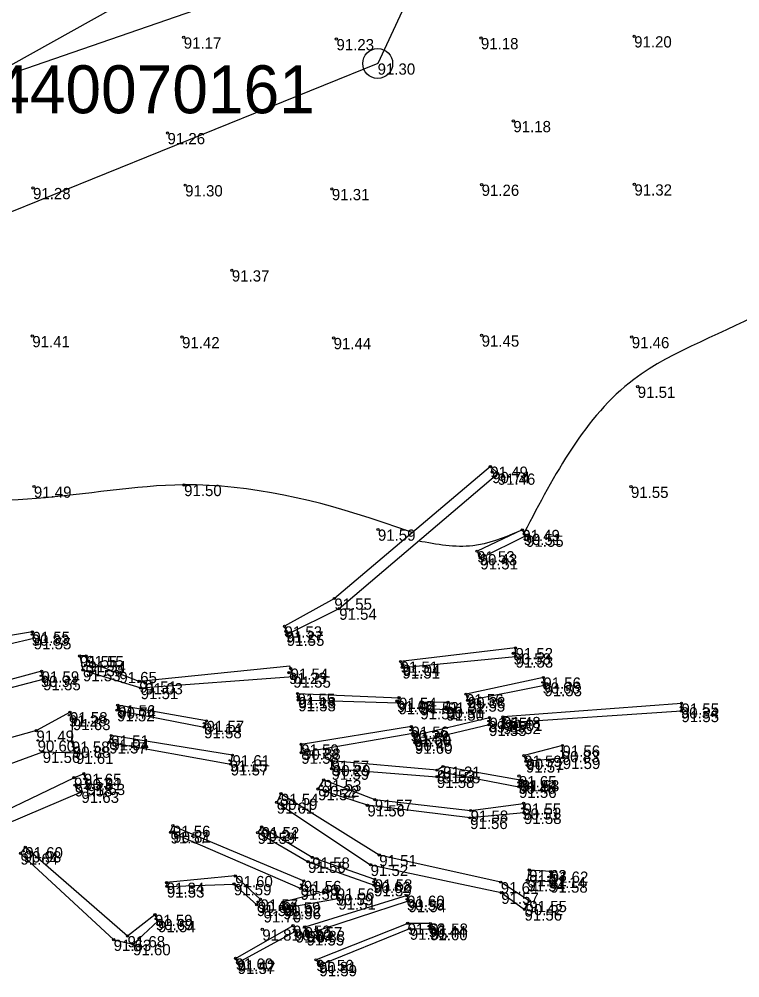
# Model space of a CAD drawing. Extents: x 316000 to 728450, y 314368 to 726000.
# Drawn here: x 725985.1 to 726225.7, y 315550.4 to 315870.5 of the extents above; entities that cross this region are included whole.
import ezdxf

# ---------------------------------------------------------------- set-up
doc = ezdxf.new("R2010")
doc.units = 0
for name, color, linetype in [('10', 7, 'Continuous'), ('24', 7, 'Continuous'), ('59', 7, 'Continuous'), ('HIDG_ELEM_####_####_#', 7, 'Continuous'), ('HIDG_GRAV_####_####_#', 7, 'Continuous'), ('RAMI_UZMR_####_####_#', 7, 'Continuous'), ('RELJ_AATZ_####_TKST_#', 7, 'Continuous'), ('RELJ_ELEM_####_####_#', 7, 'Continuous'), ('RELJ_HORZ_PAMT_####_#', 7, 'Continuous'), ('RELJ_NOGA_####_####_#', 7, 'Continuous')]:
    doc.layers.add(name, color=color, linetype=linetype)

msp = doc.modelspace()

# ---------------------------------------------------------------- linework, layer by layer
at = {"layer": '10'}
msp.add_circle((726104.77, 315855.74), 5, dxfattribs=at)
at = {"layer": '24'}
for p, q in [((726207.18, 316075.15), (726104.77, 315855.74)), ((726064.11, 315880.58), (725858.2, 315809.4)), ((726104.77, 315855.74), (725891.35, 315769.28))]:
    msp.add_line(p, q, dxfattribs=at)
at = {"layer": 'HIDG_ELEM_####_####_#'}
for centre in [(726143, 315719.32), (726153.49, 315698.65), (726138.81, 315691.88), (726074.12, 315666.08), (725989.22, 315665.03), (726150.07, 315658.75), (726007.24, 315654.78), (726113.08, 315654.96), (725992.27, 315651.23), (726075.17, 315652.25), (726027.17, 315648.78), (726159.77, 315649.04), (726078.33, 315644.09), (726111.18, 315642.84), (726134.88, 315644.17), (726018.16, 315640.71), (726127.64, 315640.86), (726206.01, 315640.73), (726001.65, 315638.05), (726147.28, 315636.57), (726046.73, 315635.38), (726115.69, 315633.07), (726141.74, 315636.09), (726015.83, 315630.07), (726117.25, 315629.89), (725991.21, 315629.64), (726002.99, 315627.6), (726079.86, 315626.93), (726154.44, 315623.57), (726166.25, 315626.08), (726055.39, 315622.97), (726089.81, 315621.42), (726006.78, 315616.78), (726086.09, 315614.52), (726151.71, 315615.59), (726072.09, 315610.2), (726153.04, 315606.94), (726036.49, 315599.24), (726065.62, 315599.79), (725986.55, 315592.63), (726103.26, 315582.42), (726155.35, 315584.71), (726161.79, 315584.06), (726079.11, 315581.52), (726064.74, 315575.79), (726090.72, 315578.33), (726114.45, 315576.61), (726073.4, 315574.64), (726154.14, 315575.01), (726030.67, 315570.02), (726076.82, 315566.55), (726081.3, 315566.04), (726121.77, 315567.65), (726057.93, 315556.25), (726085.14, 315555.68)]:
    msp.add_circle(centre, 0.225, dxfattribs=at)
at = {"layer": 'HIDG_GRAV_####_####_#'}
for points in [[(726073.66, 315667.76), (726074.41, 315664.99), (726091.92, 315673.69), (726144.85, 315718.79), (726142.39, 315721.11), (726090.3, 315677.06), (726073.66, 315667.76)], [(726137.95, 315692.86), (726139.05, 315690.52), (726154.31, 315698.07), (726153.07, 315699.99), (726137.95, 315692.86)], [(725971.42, 315662.89), (725972.67, 315659.82), (725989.93, 315663.82), (725989.49, 315665.92), (725971.42, 315662.89)], [(726112.4, 315656.01), (726113.03, 315654.06), (726150.83, 315657.71), (726150.78, 315660.52), (726112.4, 315656.01)], [(726008.23, 315655.95), (726007.42, 315657.87), (726005.29, 315657.85), (726006.36, 315653.15), (726025.63, 315647.19), (726076.58, 315651.01), (726075.42, 315654.44), (726025.17, 315649.38), (726008.23, 315655.95)], [(725947, 315640.41), (725947.4, 315638.23), (725993.06, 315650.14), (725992.55, 315652.74), (725947, 315640.41)], [(726134.27, 315645.11), (726134.79, 315643), (726160.44, 315648.16), (726160.1, 315650.67), (726134.27, 315645.11)], [(726111.91, 315643.92), (726111.73, 315642.13), (726078.25, 315643.12), (726078.05, 315645.31), (726111.91, 315643.92)], [(726017.97, 315641.42), (726017.73, 315639.76), (726046.83, 315634.1), (726047.62, 315636.2), (726017.97, 315641.42)], [(726119.29, 315642.48), (726119.01, 315640.43), (726127.73, 315640), (726128.24, 315642.37), (726119.29, 315642.48)], [(726146.64, 315637.5), (726146.7, 315635.52), (726206.19, 315639.5), (726206.22, 315642), (726146.64, 315637.5)], [(725961.77, 315624.89), (725965.2, 315615.66), (725992.91, 315625.87), (726004, 315625.55), (726002.67, 315629.29), (726003.02, 315636.83), (726002.03, 315639.09), (725990.81, 315632.94), (725961.77, 315624.89)], [(726142.11, 315637.26), (726141.95, 315634.87), (726117.19, 315628.94), (726116.81, 315631.3), (726142.11, 315637.26)], [(726079.23, 315628.32), (726079.27, 315625.6), (726116.55, 315632.09), (726116.04, 315634.27), (726079.23, 315628.32)], [(726015.78, 315631.3), (726015.12, 315629.03), (726055.71, 315621.71), (726056.28, 315624.72), (726015.78, 315631.3)], [(726153.67, 315624.58), (726154.26, 315622.67), (726166.57, 315623.84), (726166.49, 315627.96), (726153.67, 315624.58)], [(726089.35, 315622.87), (726089.35, 315620.25), (726124.54, 315617.51), (726126.5, 315619.06), (726151.96, 315614.2), (726152.32, 315616.35), (726126.61, 315620.93), (726124.62, 315619.71), (726089.35, 315622.87)], [(725965.8, 315599.1), (725967.37, 315596.09), (726005.84, 315612.53), (726003.63, 315614.7), (726007.88, 315615.15), (726006.65, 315618.54), (726003.38, 315617.21), (725965.8, 315599.1)], [(726153.48, 315608.61), (726153.62, 315605.48), (726135.63, 315603.8), (726101.33, 315608.01), (726084.88, 315613.42), (726086.77, 315616.44), (726103.83, 315609.87), (726135.8, 315606.24), (726153.48, 315608.61)], [(726072.46, 315611.83), (726071.06, 315608.94), (726102.41, 315588.11), (726146.04, 315578.8)], [(726145.87, 315582.31), (726105.29, 315591.35), (726072.46, 315611.83)], [(726035.58, 315598.99), (726036.38, 315601.14), (726080.09, 315582.74), (726079.03, 315580.18), (726035.58, 315598.99)], [(726064.7, 315598.85), (726081.53, 315589.14), (726103.55, 315581.33), (726103.81, 315583.25), (726082.93, 315590.56), (726066.03, 315600.7), (726064.7, 315598.85)], [(725987.1, 315594.01), (725985.49, 315591.9), (726016.61, 315563.09), (726023.09, 315561.62), (726031.43, 315569.34), (726030.39, 315571.42), (726021.24, 315564.3), (725987.1, 315594.01)], [(726155.37, 315586.36), (726154.76, 315582.96), (726162.37, 315582.55), (726162.55, 315585.85), (726155.37, 315586.36)], [(726034.3, 315582.14), (726034.39, 315580.91), (726056.76, 315581.68), (726064.39, 315574.73), (726065.64, 315576.57), (726057.2, 315584.38), (726034.3, 315582.14)], [(726146.04, 315578.8), (726153.8, 315573.21), (726155.39, 315576.05), (726145.87, 315582.31)], [(726073.1, 315575.61), (726073.24, 315573.67), (726091.62, 315576.87), (726091.12, 315580.22), (726073.1, 315575.61)], [(726080.4, 315567.3), (726081.03, 315564.91), (726115.03, 315576.03), (726114.6, 315577.81), (726080.4, 315567.3)], [(726076.5, 315567.8), (726077.4, 315565.89), (726058.02, 315555.39), (726057.33, 315556.83), (726076.5, 315567.8)], [(726084.19, 315556.36), (726085.31, 315554.63), (726115.49, 315566.82), (726122.24, 315566.65), (726122.35, 315568.49), (726114.79, 315568.52), (726084.19, 315556.36)]]:
    msp.add_lwpolyline(points, dxfattribs=at)
at = {"layer": 'RAMI_UZMR_####_####_#'}
msp.add_lwpolyline([(727254.69, 315085.95), (727002.7, 315002.84), (726508.21, 314868.03), (726416.7, 314837.05), (725982.38, 314530.96), (725916.44, 314513.26), (725799.16, 314549.2), (725735.9, 314623.63), (725701.82, 314711.1), (725697.25, 315112.64), (725659.91, 315163.35), (725614.81, 315211.65), (725561.8, 315231.45), (725500.09, 315274.21), (725474.77, 315308.26), (725484.26, 315374.77), (725505.03, 315405.04), (725554.87, 315404.25), (725559.14, 315567.14), (725558.67, 315591.68), (725662, 315676.73), (726089.69, 315915.19)], dxfattribs=at)
at = {"layer": 'RELJ_ELEM_####_####_#'}
for centre in [(726040.02, 315864.45), (726091, 315863.9), (726139.24, 315864.25), (726190.42, 315864.84), (726150.07, 315836.55), (726034.58, 315832.53), (725989.68, 315814.18), (726040.48, 315815.1), (726089.47, 315813.83), (726139.48, 315815.28), (726190.5, 315815.38), (726056.07, 315786.67), (725989.44, 315764.72), (726039.44, 315764.37), (726139.49, 315764.92), (726189.62, 315764.39), (726090.06, 315764.08), (726191.61, 315747.81), (726142.39, 315721.11), (726143, 315719.32), (726144.85, 315718.79), (725989.97, 315714.46), (726040.13, 315715), (726189.34, 315714.39), (726104.85, 315700.1), (726153.07, 315699.99), (726154.31, 315698.07), (726137.95, 315692.86), (726139.05, 315690.52), (726090.3, 315677.06), (726091.92, 315673.69), (725989.49, 315665.92), (726073.66, 315667.76), (726074.13, 315666.07), (726074.41, 315664.99), (726150.07, 315658.75), (726150.78, 315660.52), (726005.29, 315657.85), (726007.43, 315657.86), (726008.15, 315656.15), (726112.4, 315656.01), (726150.83, 315657.71), (725992.55, 315652.74), (726006.36, 315653.15), (726007.24, 315654.78), (726018.51, 315652.53), (726075.17, 315652.25), (726075.69, 315653.66), (726113.03, 315654.06), (726113.12, 315654.92), (725993.06, 315650.14), (726025.17, 315649.38), (726076.58, 315651.01), (726160.1, 315650.67), (726025.63, 315647.19), (726027.17, 315648.78), (726160.44, 315648.16), (726078, 315645.31), (726078.25, 315643.12), (726078.29, 315644.13), (726111.18, 315642.84), (726111.91, 315643.92), (726134.27, 315645.11), (726134.79, 315643), (726017.73, 315639.76), (726017.97, 315641.42), (726111.73, 315642.13), (726119.01, 315640.43), (726119.29, 315642.48), (726127.64, 315640.86), (726127.73, 315640), (726128.24, 315642.37), (726206.19, 315639.5), (726206.22, 315642), (726002.03, 315639.09), (726003.02, 315636.83), (726047.62, 315636.2), (726142.11, 315637.26), (726146.64, 315637.5), (725990.81, 315632.94), (726046.83, 315634.1), (726116.04, 315634.27), (726141.95, 315634.87), (726146.7, 315635.52), (726015.78, 315631.3), (726116.55, 315632.09), (726116.81, 315631.3), (726002.67, 315629.29), (726015.12, 315629.03), (726079.23, 315628.32), (726117.19, 315628.94), (726166.49, 315627.96), (725992.91, 315625.87), (726004, 315625.55), (726056.28, 315624.72), (726079.27, 315625.6), (726153.67, 315624.58), (726166.57, 315623.84), (726055.71, 315621.71), (726089.35, 315622.87), (726089.35, 315620.25), (726126.61, 315620.93), (726154.26, 315622.67), (726003.38, 315617.21), (726006.65, 315618.54), (726124.54, 315617.51), (726124.62, 315619.71), (726126.5, 315619.06), (726151.93, 315617.76), (726003.63, 315614.7), (726007.88, 315615.15), (726086.77, 315616.44), (726151.96, 315614.2), (726152.32, 315616.35), (726152.87, 315616.37), (726005.84, 315612.53), (726072.46, 315611.83), (726084.88, 315613.42), (726071.06, 315608.94), (726101.33, 315608.01), (726103.83, 315609.87), (726153.48, 315608.61), (726135.8, 315606.24), (726153.62, 315605.48), (726036.38, 315601.14), (726135.63, 315603.8), (726035.58, 315598.99), (726064.7, 315598.85), (726066.03, 315600.7), (725985.49, 315591.9), (725987.1, 315594.01), (726105.29, 315591.35), (726081.53, 315589.14), (726082.93, 315590.56), (726102.41, 315588.11), (726155.37, 315586.36), (726162.55, 315585.85), (726034.3, 315582.14), (726056.76, 315581.68), (726057.2, 315584.38), (726080.09, 315582.74), (726103.81, 315583.25), (726145.87, 315582.31), (726154.76, 315582.96), (726162.37, 315582.55), (726034.39, 315580.91), (726079.03, 315580.18), (726091.12, 315580.22), (726103.55, 315581.33), (726146.04, 315578.8), (726065.64, 315576.57), (726073.1, 315575.61), (726091.62, 315576.87), (726114.6, 315577.81), (726115.03, 315576.03), (726155.39, 315576.05), (726064.39, 315574.73), (726066.67, 315572.61), (726073.24, 315573.67), (726153.8, 315573.21), (726030.39, 315571.42), (726031.43, 315569.34), (726066.24, 315566.53), (726076.5, 315567.8), (726077.4, 315565.89), (726080.4, 315567.3), (726114.79, 315568.52), (726115.49, 315566.82), (726122.24, 315566.65), (726122.35, 315568.49), (726016.61, 315563.09), (726021.24, 315564.3), (726081.03, 315564.91), (726023.09, 315561.62), (726057.33, 315556.83), (726084.19, 315556.36), (726058.02, 315555.39), (726085.31, 315554.63)]:
    msp.add_circle(centre, 0.375, dxfattribs=at)
at = {"layer": 'RELJ_HORZ_PAMT_####_#'}
for points in [[(727407.26, 315826.81), (727420.88, 315859.78), (727421.31, 315861.98), (727420.84, 315873.16), (727415.63, 315882.87), (727395.8, 315899.43), (727371.45, 315914.61), (727360.58, 315922.6), (727355.76, 315932.78), (727350.87, 315945.8), (727343.65, 315965.03), (727334.62, 315981.5), (727324.71, 316005.53), (727317, 316014.24), (727310.95, 316025.93), (727306.22, 316036.97), (727300.2, 316049.01), (727293.8, 316067.18), (727252.55, 316104.18), (727204.11, 316093.45), (727172.31, 316071.99), (727104.82, 316081.23), (727087.15, 316092.31), (727070.62, 316103.93), (727040.63, 316117.26), (727014.6, 316106.53), (727006.58, 316100.22), (727000.85, 316096.21), (726994.11, 316090.82), (726983.98, 316084.66), (726972.39, 316080.59), (726966.37, 316079.01), (726958.49, 316076.14), (726948.07, 316071.06), (726932.7, 316067.7), (726916.22, 316058.14), (726880.98, 316039.68), (726836.99, 316020.53), (726807.52, 316005.55), (726787.17, 315993.15), (726764.31, 315989.32), (726742.06, 315986.79), (726725.03, 315990.27), (726708.15, 315999.77), (726691.28, 316009.5), (726674.31, 316013.66), (726659.02, 316010.43), (726643.66, 316003.77), (726628.26, 315996.72), (726612.85, 315992.34), (726600.2, 315993.32), (726587.04, 315996.97), (726574, 315999.47), (726567.72, 315999.1), (726561.71, 315997.03), (726548.35, 315992.52), (726536.61, 315988.25), (726525.25, 315984.49), (726513.03, 315977.96), (726485.95, 315966.35), (726456.08, 315949.13), (726439.28, 315937.58), (726388.53, 315922.53), (726290.27, 315916.68), (726240.08, 315917.6), (726226.6, 315921.61), (726211.69, 315923.04), (726191.22, 315924.62), (726136.88, 315919.22), (726111.29, 315920.51), (726086.94, 315922.23)], [(726763.5, 315809.19), (726749.16, 315806.95), (726723.09, 315811.25), (726690.49, 315817.84), (726639.53, 315820.26), (726590.09, 315809.02), (726540.4, 315816.89), (726489.33, 315851.36), (726436.89, 315851.36), (726370.59, 315850.01), (726333.14, 315821.86), (726290.46, 315814.62), (726273.5, 315803.45), (726235.67, 315774.14), (726190.27, 315750.2), (726153.69, 315699.03)], [(726116.34, 315699.09), (726105.94, 315702.69), (726040.13, 315715), (725990.82, 315710.42), (725942.03, 315708.25), (725920.28, 315706.77), (725880.37, 315714.51), (725859.05, 315708.68), (725859.05, 315672.66), (725851.26, 315613.97), (725853.47, 315568.9), (725841, 315555.79), (725885.56, 315509.63), (725935.94, 315461.49), (725983.42, 315406.25), (726032.86, 315360.51), (726082.85, 315311.19), (726122.23, 315248.76), (726137.05, 315229.29), (726180.19, 315183.1), (726194.52, 315168.27), (726211.91, 315146.93), (726212.51, 315143.16)], [(726151.59, 315699.29), (726136.52, 315694.66), (726118.39, 315696.24)]]:
    msp.add_spline(points, degree=3, dxfattribs=at)
at = {"layer": 'RELJ_NOGA_####_####_#'}
for points in [[(726259.12, 315084.51), (726262.72, 315089.26), (726261.56, 315090.84), (726260.2, 315092.42), (726257.29, 315095.53), (726218.91, 315136.38), (726180.31, 315176.84), (726128.67, 315229.97), (726063.7, 315298.11), (725999.9, 315366.09), (725937.21, 315432.09), (725876.35, 315495.23), (725810.58, 315563.08), (725744.7, 315632.91)], [(725740.86, 315626.98), (725805.54, 315558.12), (725870.39, 315491.15), (725932.8, 315426.8), (725994.98, 315360.84), (726059.66, 315292.12), (726075.75, 315275.46), (726092.08, 315259.04), (726108.47, 315242.67), (726124.69, 315226.14), (726193.27, 315154.03), (726250.06, 315092.6), (726256.32, 315085.83), (726258.82, 315084.29), (726259.12, 315084.51)]]:
    msp.add_spline(points, degree=3, dxfattribs=at)

# ---------------------------------------------------------------- texts
at = {"layer": '59'}
msp.add_text('38440070161', height=16, dxfattribs=at).set_placement((725952.89, 315839.13))
at = {"layer": 'RELJ_AATZ_####_TKST_#'}
for s, p in [('91.17', (726040.02, 315860.7)), ('91.23', (726091, 315860.15)), ('91.18', (726139.24, 315860.5)), ('91.20', (726190.42, 315861.09)), ('91.30', (726104.75, 315852.01)), ('91.18', (726150.07, 315832.8)), ('91.26', (726034.58, 315828.78)), ('91.28', (725989.68, 315810.43)), ('91.30', (726040.48, 315811.35)), ('91.31', (726089.47, 315810.08)), ('91.26', (726139.48, 315811.53)), ('91.32', (726190.5, 315811.63)), ('91.37', (726056.07, 315782.92)), ('91.41', (725989.44, 315760.97)), ('91.45', (726139.49, 315761.17)), ('91.42', (726039.44, 315760.62)), ('91.44', (726090.06, 315760.33)), ('91.46', (726189.62, 315760.64)), ('91.51', (726191.61, 315744.06)), ('91.49', (726142.39, 315717.36)), ('90.74', (726143, 315715.57)), ('91.46', (726144.85, 315715.04)), ('91.49', (725989.97, 315710.71)), ('91.50', (726040.13, 315711.25)), ('91.55', (726189.34, 315710.64)), ('91.59', (726104.85, 315696.35)), ('91.49', (726153.07, 315696.24)), ('90.51', (726153.49, 315694.9)), ('91.55', (726154.31, 315694.32)), ('91.53', (726137.95, 315689.11)), ('90.43', (726138.81, 315688.13)), ('91.51', (726139.05, 315686.77)), ('91.55', (726090.3, 315673.31)), ('91.54', (726091.92, 315669.94)), ('91.55', (725989.49, 315662.17)), ('91.53', (726073.66, 315664.01)), ('91.27', (726074.13, 315662.32)), ('90.83', (725989.22, 315661.28)), ('91.55', (725989.93, 315660.07)), ('91.55', (726074.41, 315661.24)), ('91.52', (726150.78, 315656.77)), ('91.55', (726005.29, 315654.1)), ('91.55', (726007.43, 315654.11)), ('91.54', (726008.15, 315652.4)), ('91.51', (726112.4, 315652.26)), ('90.58', (726150.07, 315655)), ('91.53', (726150.83, 315653.96)), ('91.59', (725992.55, 315648.99)), ('91.53', (726006.36, 315649.4)), ('91.30', (726007.24, 315651.03)), ('91.65', (726018.51, 315648.78)), ('91.54', (726075.69, 315649.91)), ('91.51', (726113.03, 315650.31)), ('91.04', (726113.12, 315651.17)), ('90.94', (725992.27, 315647.48)), ('91.55', (725993.06, 315646.39)), ('91.51', (726025.17, 315645.63)), ('91.23', (726075.17, 315648.5)), ('91.55', (726076.58, 315647.26)), ('91.56', (726160.1, 315646.92)), ('91.51', (726025.63, 315643.44)), ('91.03', (726027.17, 315645.03)), ('90.06', (726159.77, 315645.29)), ('91.53', (726160.44, 315644.41)), ('91.55', (726078, 315641.56)), ('91.53', (726078.25, 315639.37)), ('91.18', (726078.29, 315640.38)), ('91.05', (726111.18, 315639.09)), ('91.54', (726111.91, 315640.17)), ('91.56', (726134.27, 315641.36)), ('91.55', (726134.79, 315639.25)), ('90.38', (726134.88, 315640.42)), ('91.52', (726017.73, 315636.01)), ('91.56', (726017.97, 315637.67)), ('90.74', (726018.16, 315636.96)), ('91.54', (726111.73, 315638.38)), ('91.51', (726119.01, 315636.68)), ('91.52', (726119.29, 315638.73)), ('90.51', (726127.64, 315637.11)), ('91.50', (726127.73, 315636.25)), ('91.52', (726128.24, 315638.62)), ('90.34', (726206.01, 315636.98)), ('91.55', (726206.22, 315638.25)), ('91.28', (726001.65, 315634.3)), ('91.58', (726002.03, 315635.34)), ('91.63', (726003.02, 315633.08)), ('91.55', (726142.11, 315633.51)), ('91.48', (726146.64, 315633.75)), ('90.01', (726147.28, 315632.82)), ('91.55', (726206.19, 315635.75)), ('91.14', (726046.73, 315631.63)), ('91.58', (726046.83, 315630.35)), ('91.57', (726047.62, 315632.45)), ('91.56', (726116.04, 315630.52)), ('89.85', (726141.74, 315632.34)), ('91.55', (726141.95, 315631.12)), ('91.52', (726146.7, 315631.77)), ('91.49', (725990.81, 315629.19)), ('91.51', (726015.78, 315627.55)), ('91.04', (726015.83, 315626.32)), ('90.29', (726115.69, 315629.32)), ('91.50', (726116.55, 315628.34)), ('91.60', (726116.81, 315627.55)), ('90.60', (725991.21, 315625.89)), ('91.58', (726002.67, 315625.54)), ('90.88', (726002.99, 315623.85)), ('91.57', (726015.12, 315625.28)), ('91.59', (726079.23, 315624.57)), ('90.88', (726079.86, 315623.18)), ('91.60', (726117.19, 315625.19)), ('90.45', (726117.25, 315626.14)), ('91.56', (726166.49, 315624.21)), ('91.56', (725992.91, 315622.12)), ('91.61', (726004, 315621.8)), ('91.61', (726056.28, 315620.97)), ('91.58', (726079.27, 315621.85)), ('91.59', (726153.67, 315620.83)), ('90.83', (726166.25, 315622.33)), ('91.59', (726166.57, 315620.09)), ('91.15', (726055.39, 315619.22)), ('91.57', (726055.71, 315617.96)), ('91.57', (726089.35, 315619.12)), ('90.29', (726089.81, 315617.67)), ('91.21', (726126.61, 315617.18)), ('91.57', (726154.26, 315618.92)), ('90.71', (726154.44, 315619.82)), ('91.53', (726003.38, 315613.46)), ('91.65', (726006.65, 315614.79)), ('91.59', (726089.35, 315616.5)), ('91.58', (726124.54, 315613.76)), ('91.53', (726124.62, 315615.96)), ('91.55', (726126.5, 315615.31)), ('91.65', (726151.93, 315614.01)), ('91.58', (726003.63, 315610.95)), ('90.61', (726006.78, 315613.03)), ('91.63', (726007.88, 315611.4)), ('90.22', (726086.09, 315610.77)), ('91.53', (726086.77, 315612.69)), ('90.48', (726151.71, 315611.84)), ('91.56', (726151.96, 315610.45)), ('91.54', (726152.32, 315612.6)), ('91.63', (726152.87, 315612.62)), ('91.63', (726005.84, 315608.78)), ('91.54', (726072.46, 315608.08)), ('91.54', (726084.88, 315609.67)), ('91.61', (726071.06, 315605.19)), ('90.19', (726072.09, 315606.45)), ('91.56', (726101.33, 315604.26)), ('91.57', (726103.83, 315606.12)), ('91.55', (726153.48, 315604.86)), ('91.58', (726135.8, 315602.49)), ('90.51', (726153.04, 315603.19)), ('91.58', (726153.62, 315601.73)), ('91.56', (726135.63, 315600.05)), ('91.57', (726035.58, 315595.24)), ('91.56', (726036.38, 315597.39)), ('90.81', (726036.49, 315595.49)), ('91.59', (726064.7, 315595.1)), ('90.24', (726065.62, 315596.04)), ('91.52', (726066.03, 315596.95)), ('91.64', (725985.49, 315588.15)), ('90.98', (725986.55, 315588.88)), ('91.60', (725987.1, 315590.26)), ('91.56', (726081.53, 315585.39)), ('91.58', (726082.93, 315586.81)), ('91.51', (726105.29, 315587.6)), ('91.52', (726102.41, 315584.36)), ('91.63', (726155.37, 315582.61)), ('91.62', (726162.55, 315582.1)), ('91.34', (726034.3, 315578.39)), ('91.60', (726057.2, 315580.63)), ('91.56', (726080.09, 315578.99)), ('90.62', (726103.26, 315578.67)), ('91.58', (726103.81, 315579.5)), ('91.64', (726145.87, 315578.56)), ('91.54', (726154.76, 315579.21)), ('91.11', (726155.35, 315580.96)), ('91.14', (726161.79, 315580.31)), ('91.58', (726162.37, 315578.8)), ('91.53', (726034.39, 315577.16)), ('91.59', (726056.76, 315577.93)), ('91.58', (726079.03, 315576.43)), ('90.46', (726079.11, 315577.77)), ('91.56', (726091.12, 315576.47)), ('91.59', (726103.55, 315577.58)), ('91.57', (726146.04, 315575.05)), ('90.64', (726064.74, 315572.04)), ('91.57', (726065.64, 315572.82)), ('91.59', (726073.1, 315571.86)), ('90.59', (726090.72, 315574.58)), ('91.51', (726091.62, 315573.12)), ('90.56', (726114.45, 315572.86)), ('91.60', (726114.6, 315574.06)), ('91.54', (726115.03, 315572.28)), ('91.55', (726155.39, 315572.3)), ('91.53', (726064.39, 315570.98)), ('91.70', (726066.67, 315568.86)), ('91.56', (726073.24, 315569.92)), ('90.92', (726073.4, 315570.89)), ('91.56', (726153.8, 315569.46)), ('90.42', (726154.14, 315571.26)), ('91.59', (726030.39, 315567.67)), ('90.69', (726030.67, 315566.27)), ('91.54', (726031.43, 315565.59)), ('91.81', (726066.24, 315562.78)), ('91.52', (726076.5, 315564.05)), ('90.80', (726076.82, 315562.8)), ('91.57', (726080.4, 315563.55)), ('90.88', (726081.3, 315562.29)), ('91.62', (726114.79, 315564.77)), ('91.55', (726115.49, 315563.07)), ('90.44', (726121.77, 315563.9)), ('91.60', (726122.24, 315562.9)), ('91.58', (726122.35, 315564.74)), ('91.63', (726016.61, 315559.34)), ('91.68', (726021.24, 315560.55)), ('91.64', (726077.4, 315562.14)), ('91.55', (726081.03, 315561.16)), ('91.60', (726023.09, 315557.87)), ('91.60', (726057.33, 315553.08)), ('91.42', (726057.93, 315552.5)), ('91.57', (726058.02, 315551.64)), ('91.56', (726084.19, 315552.61)), ('90.81', (726085.14, 315551.93)), ('91.59', (726085.31, 315550.88))]:
    msp.add_text(s, height=3.75, dxfattribs=at).set_placement(p)

doc.saveas('drawing.dxf')
